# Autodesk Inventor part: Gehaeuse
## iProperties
Created: 2006-08
Part Number: Gehaeuse
Material: Stahl
Document SubType Name: Sheet Metal
Designer: trainee
Author: trainee
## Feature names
1. Grobblech6
2. Grobblech7
3. Biegung5
